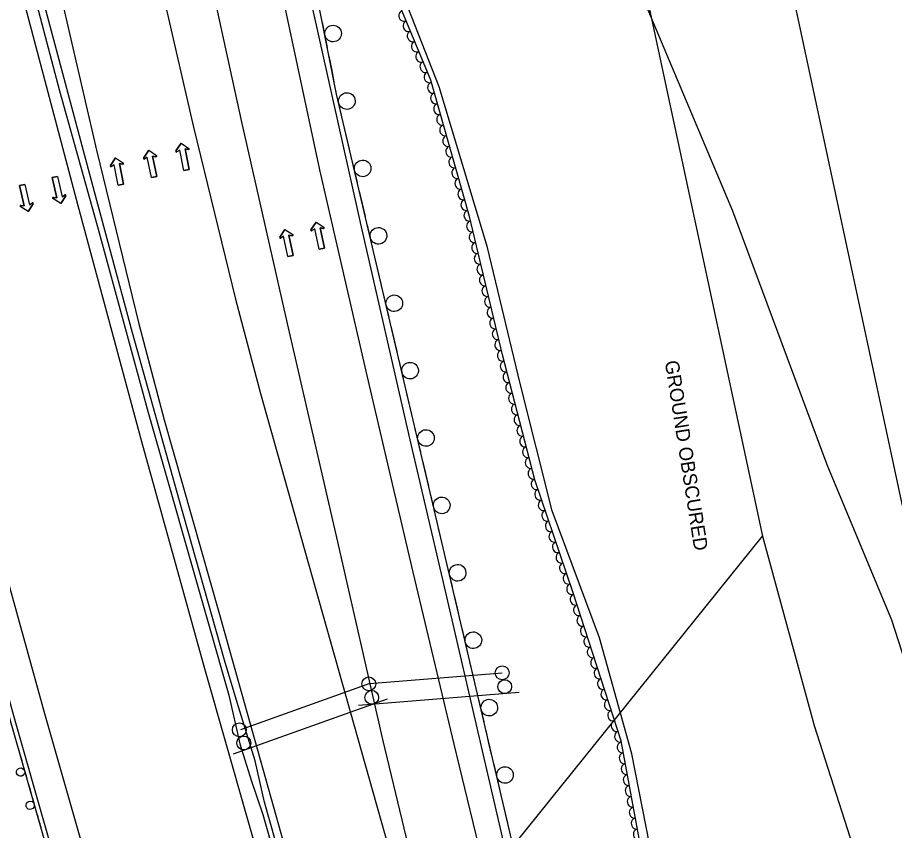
# Model space of a CAD drawing. Extents: x 1746719 to 1766531, y 631721 to 662391.
# Drawn here: x 1753970.5 to 1754287.2, y 650890.3 to 651183.8 of the extents above; entities that cross this region are included whole.
import ezdxf

# ---------------------------------------------------------------- set-up
doc = ezdxf.new("R2010")
doc.units = 0
for name, color, linetype in [('SURVEY - AERIAL SURVEY - Photo Control - Points - Elevations', 7, 'Continuous'), ('SURVEY - AERIAL SURVEY - Photo Control - Points - Locators', 7, 'Continuous'), ('SURVEY - AERIAL SURVEY - Photo Control - Points - Numbers', 7, 'Continuous'), ('SURVEY - AERIAL SURVEY - Photo Control with Text', 7, 'Continuous'), ('SURVEY - CONTROL - Grid', 7, 'Continuous'), ('SURVEY - CONTROL - Points - Locators', 7, 'Continuous')]:
    doc.layers.add(name, color=color, linetype=linetype)

msp = doc.modelspace()

# ---------------------------------------------------------------- linework, layer by layer
at = {"layer": 'SURVEY - AERIAL SURVEY - Photo Control - Points - Elevations'}
for points in [[(1754063.35, 651204.56), (1754079.53, 651128.87), (1754096.68, 651054.56), (1754113.23, 650983.52), (1754128.08, 650921.41), (1754151.45, 650825.16), (1754182.39, 650697.84)], [(1754072.82, 651206.04), (1754094.18, 651109.83), (1754112.14, 651031.33), (1754123.49, 650982.98), (1754145.46, 650887.82), (1754164.53, 650808.3), (1754187.99, 650714.26), (1754218.11, 650592.11), (1754265.98, 650448.02)], [(1754020.74, 651201.91), (1754034.03, 651144.22), (1754049.15, 651082.15), (1754058.18, 651048.02), (1754078.02, 650978.02), (1754103.01, 650889.26), (1754131.48, 650789.68), (1754151.45, 650719.85)], [(1754039.38, 651201.31), (1754051.19, 651146.66), (1754067.85, 651073.3), (1754085.71, 650996.02), (1754102.41, 650922.67), (1754117.55, 650859.55), (1754134.13, 650790.75), (1754151.45, 650719.85)], [(1753972.17, 651192.06), (1753992.25, 651116.01), (1754015.21, 651030.74), (1754038.02, 650948.81), (1754060.55, 650869.78), (1754089.76, 650767.41), (1754112.32, 650689.17), (1754146.8, 650566.94), (1754158.11, 650527.42), (1754160.85, 650517.83)], [(1753985.66, 651193.84), (1753999, 651135.92), (1754014.26, 651073.28), (1754023.46, 651038.51), (1754043.38, 650968.24), (1754068.37, 650879.43), (1754096.87, 650779.78), (1754126.64, 650675.65), (1754149.99, 650593.47), (1754178.2, 650495.46), (1754179.47, 650490.6)], [(1753914.16, 651176.74), (1753934.28, 651100.55), (1753957.34, 651014.89), (1753980.27, 650932.54), (1754002.85, 650853.32), (1754032.08, 650750.87), (1754054.62, 650672.71), (1754094.66, 650530.79)], [(1753903.52, 651173.93), (1753923.65, 651097.71), (1753946.73, 651011.99), (1753969.68, 650929.56), (1753992.27, 650850.31), (1754021.51, 650747.83), (1754044.04, 650669.7), (1754081.42, 650537.19)]]:
    msp.add_lwpolyline(points, dxfattribs=at)
at = {"layer": 'SURVEY - AERIAL SURVEY - Photo Control - Points - Locators'}
for p, q in [((1754027.68, 651135.66), (1754029.56, 651138.47)), ((1754029.56, 651138.47), (1754027.68, 651135.66)), ((1754029.56, 651138.47), (1754032.37, 651136.59)), ((1754029.56, 651138.47), (1754032.37, 651136.59)), ((1754015.99, 651133.1), (1754017.86, 651135.91)), ((1754017.86, 651135.91), (1754015.99, 651133.1)), ((1754017.86, 651135.91), (1754020.67, 651134.04)), ((1754017.86, 651135.91), (1754020.67, 651134.04)), ((1754029.05, 651136), (1754028.03, 651135.32)), ((1754029.05, 651136), (1754028.03, 651135.32)), ((1754030.52, 651128.62), (1754029.05, 651136)), ((1754030.52, 651128.62), (1754029.05, 651136)), ((1754032.18, 651136.14), (1754030.98, 651136.39)), ((1754030.98, 651136.39), (1754032.45, 651129.01)), ((1754032.45, 651129.01), (1754030.98, 651136.39)), ((1754030.98, 651136.39), (1754032.18, 651136.14)), ((1754004.03, 651130.37), (1754005.91, 651133.18)), ((1754005.91, 651133.18), (1754004.03, 651130.37)), ((1754005.91, 651133.18), (1754008.72, 651131.3)), ((1754005.91, 651133.18), (1754008.72, 651131.3)), ((1754017.35, 651133.45), (1754016.33, 651132.76)), ((1754017.35, 651133.45), (1754016.33, 651132.76)), ((1754018.82, 651126.07), (1754017.35, 651133.45)), ((1754018.82, 651126.07), (1754017.35, 651133.45)), ((1754020.49, 651133.59), (1754019.28, 651133.83)), ((1754019.28, 651133.83), (1754020.75, 651126.45)), ((1754020.75, 651126.45), (1754019.28, 651133.83)), ((1754019.28, 651133.83), (1754020.49, 651133.59)), ((1754005.4, 651130.71), (1754004.38, 651130.03)), ((1754005.4, 651130.71), (1754004.38, 651130.03)), ((1754006.87, 651123.34), (1754005.4, 651130.71)), ((1754006.87, 651123.34), (1754005.4, 651130.71)), ((1754008.53, 651130.86), (1754007.33, 651131.1)), ((1754007.33, 651131.1), (1754008.8, 651123.72)), ((1754008.8, 651123.72), (1754007.33, 651131.1)), ((1754007.33, 651131.1), (1754008.53, 651130.86)), ((1754032.45, 651129.01), (1754030.52, 651128.62)), ((1754030.52, 651128.62), (1754032.45, 651129.01)), ((1753983.01, 651126.03), (1753984.93, 651126.46)), ((1753984.93, 651126.46), (1753983.01, 651126.03)), ((1753984.67, 651118.69), (1753983.01, 651126.03)), ((1753983.01, 651126.03), (1753984.67, 651118.69)), ((1753984.93, 651126.46), (1753986.59, 651119.13)), ((1753984.93, 651126.46), (1753986.59, 651119.13)), ((1754020.75, 651126.45), (1754018.82, 651126.07)), ((1754018.82, 651126.07), (1754020.75, 651126.45)), ((1753971.22, 651123.14), (1753973.14, 651123.57)), ((1753973.14, 651123.57), (1753971.22, 651123.14)), ((1753972.88, 651115.8), (1753971.22, 651123.14)), ((1753971.22, 651123.14), (1753972.88, 651115.8)), ((1753973.14, 651123.57), (1753974.79, 651116.24)), ((1753973.14, 651123.57), (1753974.79, 651116.24)), ((1754008.8, 651123.72), (1754006.87, 651123.34)), ((1754006.87, 651123.34), (1754008.8, 651123.72)), ((1753987.94, 651119.5), (1753986.14, 651116.65)), ((1753986.14, 651116.65), (1753987.94, 651119.5)), ((1753986.59, 651119.13), (1753987.59, 651119.84)), ((1753986.59, 651119.13), (1753987.59, 651119.84)), ((1753971.66, 651116.01), (1753972.88, 651115.8)), ((1753972.88, 651115.8), (1753971.66, 651116.01)), ((1753976.15, 651116.61), (1753974.35, 651113.76)), ((1753974.35, 651113.76), (1753976.15, 651116.61)), ((1753974.79, 651116.24), (1753975.8, 651116.95)), ((1753974.79, 651116.24), (1753975.8, 651116.95)), ((1753986.14, 651116.65), (1753983.28, 651118.45)), ((1753986.14, 651116.65), (1753983.28, 651118.45)), ((1753983.46, 651118.9), (1753984.67, 651118.69)), ((1753984.67, 651118.69), (1753983.46, 651118.9)), ((1753974.35, 651113.76), (1753971.49, 651115.56)), ((1753974.35, 651113.76), (1753971.49, 651115.56)), ((1754076.46, 651107.14), (1754078.29, 651109.97)), ((1754078.29, 651109.97), (1754076.46, 651107.14)), ((1754078.29, 651109.97), (1754081.13, 651108.13)), ((1754078.29, 651109.97), (1754081.13, 651108.13)), ((1754065.2, 651104.51), (1754067.04, 651107.34)), ((1754067.04, 651107.34), (1754065.2, 651104.51)), ((1754067.04, 651107.34), (1754069.87, 651105.5)), ((1754067.04, 651107.34), (1754069.87, 651105.5)), ((1754077.82, 651107.49), (1754076.8, 651106.8)), ((1754077.82, 651107.49), (1754076.8, 651106.8)), ((1754079.39, 651100.14), (1754077.82, 651107.49)), ((1754079.39, 651100.14), (1754077.82, 651107.49)), ((1754080.95, 651107.68), (1754079.74, 651107.91)), ((1754079.74, 651107.91), (1754081.31, 651100.55)), ((1754081.31, 651100.55), (1754079.74, 651107.91)), ((1754079.74, 651107.91), (1754080.95, 651107.68)), ((1754066.56, 651104.86), (1754065.55, 651104.17)), ((1754066.56, 651104.86), (1754065.55, 651104.17)), ((1754068.13, 651097.51), (1754066.56, 651104.86)), ((1754068.13, 651097.51), (1754066.56, 651104.86)), ((1754069.69, 651105.05), (1754068.49, 651105.28)), ((1754068.49, 651105.28), (1754070.05, 651097.92)), ((1754070.05, 651097.92), (1754068.49, 651105.28)), ((1754068.49, 651105.28), (1754069.69, 651105.05)), ((1754081.31, 651100.55), (1754079.39, 651100.14)), ((1754079.39, 651100.14), (1754081.31, 651100.55)), ((1754070.05, 651097.92), (1754068.13, 651097.51)), ((1754068.13, 651097.51), (1754070.05, 651097.92))]:
    msp.add_line(p, q, dxfattribs=at)
for points in [[(1754189.03, 651208.12), (1754228.69, 651114.03), (1754262.75, 651022.48), (1754286.04, 650966.3), (1754304.12, 650910.31), (1754324.95, 650850.75), (1754345.91, 650775.28), (1754364.89, 650696.63), (1754384.99, 650630.7), (1754403.46, 650583.55), (1754431.21, 650499.72), (1754438.06, 650449.83), (1754446.98, 650357.55)], [(1754289.04, 650635.59), (1754285.74, 650671.74), (1754281.36, 650715.71), (1754272.07, 650753.89), (1754248.97, 650769.35), (1754231.19, 650774.34), (1754216.19, 650821.21), (1754201.2, 650872.56), (1754192.32, 650917.96), (1754180.65, 650959.8), (1754163.54, 651005.75), (1754152.03, 651051.69), (1754140.15, 651100.82), (1754122.75, 651158.86), (1754106.53, 651200.34)]]:
    msp.add_lwpolyline(points, dxfattribs=at)
for centre, start, end in [((1754027.89, 651135.52), 146.2595, 303.7527), ((1754027.89, 651135.52), 146.2595, 303.7527), ((1754032.23, 651136.39), 258.8112, 56.2595), ((1754032.23, 651136.39), 258.8112, 56.2595), ((1754016.19, 651132.97), 146.2595, 303.7527), ((1754016.19, 651132.97), 146.2595, 303.7527), ((1754020.54, 651133.83), 258.8112, 56.2595), ((1754020.54, 651133.83), 258.8112, 56.2595), ((1754004.24, 651130.24), 146.2595, 303.7527), ((1754004.24, 651130.24), 146.2595, 303.7527), ((1754008.58, 651131.1), 258.8112, 56.2595), ((1754008.58, 651131.1), 258.8112, 56.2595), ((1753987.73, 651119.63), 327.7185, 125.2117), ((1753987.73, 651119.63), 327.7185, 125.2117), ((1753971.62, 651115.77), 80.2702, 237.7185), ((1753971.62, 651115.77), 80.2702, 237.7185), ((1753975.94, 651116.74), 327.7185, 125.2117), ((1753975.94, 651116.74), 327.7185, 125.2117), ((1753983.41, 651118.66), 80.2702, 237.7185), ((1753983.41, 651118.66), 80.2702, 237.7185), ((1754076.66, 651107), 147.0491, 304.5422), ((1754076.66, 651107), 147.0491, 304.5422), ((1754080.99, 651107.93), 259.6008, 57.0491), ((1754080.99, 651107.93), 259.6008, 57.0491), ((1754065.41, 651104.37), 147.0491, 304.5422), ((1754065.41, 651104.37), 147.0491, 304.5422), ((1754069.74, 651105.29), 259.6008, 57.0491), ((1754069.74, 651105.29), 259.6008, 57.0491)]:
    msp.add_arc(centre, 0.246, start, end, dxfattribs=at)
at = {"layer": 'SURVEY - AERIAL SURVEY - Photo Control - Points - Numbers'}
for points in [[(1754277.22, 650442.59), (1754261.86, 650465.35), (1754221.06, 650591.52), (1754167.3, 650808.68), (1754121.44, 651004.08), (1754085.73, 651156.22), (1754055.64, 651308.03), (1754019.01, 651484.3)], [(1753976.4, 651192.62), (1753985.63, 651157.37), (1753999.56, 651107.38), (1754017.65, 651041.27), (1754039.67, 650963.99), (1754046.76, 650939.07), (1754050.77, 650921.6), (1754055, 650908.04), (1754059.02, 650896.07), (1754079.37, 650824.52), (1754099.29, 650754.42), (1754120.26, 650679.29), (1754139.53, 650612.32), (1754166.51, 650517.9)], [(1754175.8, 650492.56), (1754160.24, 650546.46), (1754142.04, 650609.69), (1754125.24, 650668.34), (1754110.86, 650720.6), (1754096.24, 650772.39), (1754077.82, 650836.36), (1754059.64, 650900.45), (1754056.28, 650915.36), (1754049.84, 650936.52), (1754045.21, 650951.78), (1754029.02, 651009.31), (1754011.97, 651069.98), (1753996.6, 651127.12), (1753979.08, 651193.03)], [(1754082.4, 651173.03), (1754080.61, 651182.06)], [(1753901.95, 651173.51), (1753922.08, 651097.29), (1753945.17, 651011.56), (1753968.12, 650929.12), (1753990.71, 650849.86), (1754019.95, 650747.38), (1754042.48, 650669.25), (1754079.47, 650538.13)], [(1754083.94, 651165.28), (1754083.02, 651169.89)], [(1754084.85, 651160.67), (1754083.94, 651165.28)], [(1754087.53, 651148.57), (1754085.73, 651156.22), (1754085.47, 651157.54)], [(1754089.33, 651140.88), (1754088.26, 651145.45)], [(1754090.41, 651136.3), (1754089.33, 651140.88)], [(1754093.24, 651124.23), (1754091.14, 651133.19)], [(1754095.05, 651116.54), (1754093.97, 651121.11)], [(1754096.12, 651111.96), (1754095.05, 651116.54)], [(1754098.95, 651099.89), (1754096.85, 651108.85)], [(1754100.76, 651092.2), (1754099.68, 651096.78)], [(1754101.83, 651087.62), (1754100.76, 651092.2)], [(1754104.66, 651075.55), (1754102.56, 651084.51)], [(1754106.47, 651067.86), (1754105.4, 651072.44)], [(1754107.54, 651063.29), (1754106.47, 651067.86)], [(1754110.38, 651051.21), (1754108.27, 651060.17)], [(1754112.18, 651043.52), (1754111.11, 651048.1)], [(1754113.26, 651038.95), (1754112.18, 651043.52)], [(1754116.09, 651026.87), (1754113.99, 651035.83)], [(1754117.89, 651019.18), (1754116.82, 651023.76)], [(1754118.97, 651014.61), (1754117.89, 651019.18)], [(1754121.8, 651002.54), (1754121.44, 651004.08), (1754119.7, 651011.49)], [(1754123.6, 650994.84), (1754122.53, 650999.42)], [(1754124.68, 650990.27), (1754123.6, 650994.84)], [(1754127.51, 650978.2), (1754125.41, 650987.15)], [(1754129.32, 650970.51), (1754128.24, 650975.08)], [(1754130.39, 650965.93), (1754129.32, 650970.51)], [(1754133.22, 650953.86), (1754131.12, 650962.81)], [(1754135.03, 650946.17), (1754133.96, 650950.74)], [(1754136.1, 650941.59), (1754135.03, 650946.17)], [(1754138.94, 650929.52), (1754136.83, 650938.48)], [(1754140.74, 650921.83), (1754139.67, 650926.4)], [(1753970.72, 650920.02), (1753971.36, 650917.76)], [(1754141.82, 650917.25), (1754140.74, 650921.83)], [(1753971.36, 650917.76), (1753972, 650915.5)], [(1753972.44, 650913.96), (1753973.7, 650909.54)], [(1754144.65, 650905.18), (1754142.55, 650914.14)], [(1753974.14, 650908), (1753974.79, 650905.74)], [(1753974.79, 650905.74), (1753975.43, 650903.48)], [(1753975.87, 650901.94), (1753977.13, 650897.52)], [(1754146.45, 650897.49), (1754145.38, 650902.07)], [(1754147.53, 650892.91), (1754146.45, 650897.49)], [(1753977.57, 650895.98), (1753978.21, 650893.72)], [(1753978.21, 650893.72), (1753978.86, 650891.46)]]:
    msp.add_lwpolyline(points, dxfattribs=at)
for centre, radius, start, end in [((1754084.46, 651178.08), 3, 304.4806, 304.4666), ((1754089.41, 651153.69), 3, 306.475, 306.461), ((1754095.12, 651129.35), 3, 306.475, 306.461), ((1754100.83, 651105.01), 3, 306.475, 306.461), ((1754106.54, 651080.67), 3, 306.475, 306.461), ((1754112.26, 651056.33), 3, 306.475, 306.461), ((1754117.97, 651031.99), 3, 306.475, 306.461), ((1754123.68, 651007.66), 3, 306.475, 306.461), ((1754129.39, 650983.32), 3, 306.4774, 306.4634), ((1754135.1, 650958.98), 3, 306.4774, 306.4634), ((1754140.82, 650934.64), 3, 306.4774, 306.4634), ((1754146.53, 650910.3), 3, 306.4774, 306.4634), ((1753971.62, 650911.36), 1.5, 129.1679, 129.1581), ((1753975.05, 650899.34), 1.5, 129.1679, 129.1581)]:
    msp.add_arc(centre, radius, start, end, dxfattribs=at)
at = {"layer": 'SURVEY - AERIAL SURVEY - Photo Control with Text'}
msp.add_lwpolyline([(1754437.51, 650352.91), (1754373.46, 650364.73), (1754342.18, 650371.08), (1754330.7, 650387.52), (1754322.19, 650421.14), (1754324.94, 650470.68), (1754320.13, 650524.69), (1754316.48, 650564.69), (1754305.81, 650600.41), (1754286.82, 650634.23), (1754280.52, 650686.12), (1754274.54, 650724.16), (1754269.28, 650750.14), (1754249.03, 650765.51), (1754227.91, 650772.31), (1754210.67, 650824.74), (1754196.82, 650877.62), (1754188.5, 650922.64), (1754171.01, 650976.43), (1754157.32, 651016.92), (1754145.6, 651062.07), (1754133.69, 651111.97), (1754119.69, 651161.21), (1754098.48, 651212.49)], dxfattribs=at)
for centre, major_axis in [((1754110.06, 651184.48), (-0.76, 1.85)), ((1754111.59, 651180.78), (-0.76, 1.85)), ((1754113.12, 651177.08), (-0.76, 1.85)), ((1754114.65, 651173.39), (-0.76, 1.85)), ((1754116.18, 651169.69), (-0.76, 1.85)), ((1754117.71, 651165.99), (-0.76, 1.85)), ((1754119.23, 651162.3), (-0.76, 1.85)), ((1754120.46, 651158.5), (-0.55, 1.92)), ((1754121.55, 651154.65), (-0.55, 1.92)), ((1754122.65, 651150.8), (-0.55, 1.92)), ((1754123.74, 651146.95), (-0.55, 1.92)), ((1754124.83, 651143.11), (-0.55, 1.92)), ((1754125.93, 651139.26), (-0.55, 1.92)), ((1754127.02, 651135.41), (-0.55, 1.92)), ((1754128.12, 651131.56), (-0.55, 1.92)), ((1754129.21, 651127.72), (-0.55, 1.92)), ((1754130.31, 651123.87), (-0.55, 1.92)), ((1754131.4, 651120.02), (-0.55, 1.92)), ((1754132.49, 651116.17), (-0.55, 1.92)), ((1754133.59, 651112.33), (-0.55, 1.92)), ((1754134.53, 651108.44), (-0.46, 1.95)), ((1754135.46, 651104.55), (-0.46, 1.95)), ((1754136.39, 651100.66), (-0.46, 1.95)), ((1754137.32, 651096.77), (-0.46, 1.95)), ((1754138.25, 651092.88), (-0.46, 1.95)), ((1754139.17, 651088.99), (-0.46, 1.95)), ((1754140.1, 651085.1), (-0.46, 1.95)), ((1754141.03, 651081.2), (-0.46, 1.95)), ((1754141.96, 651077.31), (-0.46, 1.95)), ((1754142.89, 651073.42), (-0.46, 1.95)), ((1754143.82, 651069.53), (-0.46, 1.95)), ((1754144.74, 651065.64), (-0.46, 1.95)), ((1754145.68, 651061.75), (-0.5, 1.94)), ((1754146.68, 651057.88), (-0.5, 1.94)), ((1754147.69, 651054.01), (-0.5, 1.94)), ((1754148.7, 651050.14), (-0.5, 1.94)), ((1754149.7, 651046.27), (-0.5, 1.94)), ((1754150.71, 651042.39), (-0.5, 1.94)), ((1754151.71, 651038.52), (-0.5, 1.94)), ((1754152.72, 651034.65), (-0.5, 1.94)), ((1754153.72, 651030.78), (-0.5, 1.94)), ((1754154.73, 651026.91), (-0.5, 1.94)), ((1754155.73, 651023.04), (-0.5, 1.94)), ((1754156.74, 651019.16), (-0.5, 1.94)), ((1754157.86, 651015.33), (-0.64, 1.89)), ((1754159.14, 651011.54), (-0.64, 1.89)), ((1754160.42, 651007.75), (-0.64, 1.89)), ((1754161.7, 651003.96), (-0.64, 1.89)), ((1754162.99, 651000.17), (-0.64, 1.89)), ((1754164.27, 650996.38), (-0.64, 1.89)), ((1754165.55, 650992.59), (-0.64, 1.89)), ((1754166.83, 650988.8), (-0.64, 1.89)), ((1754168.11, 650985.01), (-0.64, 1.89)), ((1754169.39, 650981.22), (-0.64, 1.89)), ((1754170.67, 650977.44), (-0.64, 1.89)), ((1754171.92, 650973.64), (-0.62, 1.9)), ((1754173.16, 650969.83), (-0.62, 1.9)), ((1754174.39, 650966.03), (-0.62, 1.9)), ((1754175.63, 650962.22), (-0.62, 1.9)), ((1754176.87, 650958.42), (-0.62, 1.9)), ((1754178.1, 650954.61), (-0.62, 1.9)), ((1754179.34, 650950.81), (-0.62, 1.9)), ((1754180.58, 650947.01), (-0.62, 1.9)), ((1754181.81, 650943.2), (-0.62, 1.9)), ((1754183.05, 650939.4), (-0.62, 1.9)), ((1754184.29, 650935.59), (-0.62, 1.9)), ((1754185.52, 650931.79), (-0.62, 1.9)), ((1754186.76, 650927.99), (-0.62, 1.9)), ((1754187.99, 650924.18), (-0.62, 1.9)), ((1754188.93, 650920.3), (-0.36, 1.97)), ((1754189.66, 650916.37), (-0.36, 1.97)), ((1754190.38, 650912.43), (-0.36, 1.97)), ((1754191.11, 650908.5), (-0.36, 1.97)), ((1754191.84, 650904.57), (-0.36, 1.97)), ((1754192.56, 650900.63), (-0.36, 1.97)), ((1754193.29, 650896.7), (-0.36, 1.97)), ((1754194.02, 650892.77), (-0.36, 1.97)), ((1754194.75, 650888.83), (-0.36, 1.97))]:
    msp.add_ellipse(centre, major_axis=major_axis, ratio=0.940188, start_param=0, end_param=3.141593, dxfattribs=at)
at = {"layer": 'SURVEY - CONTROL - Grid'}
for p, q in [((1754145.49, 650947.17), (1754145.49, 650947.17)), ((1754145.49, 650947.17), (1754145.49, 650947.17)), ((1754097.72, 650943.38), (1754051.02, 650926.57)), ((1754097.72, 650943.38), (1754051.02, 650926.57)), ((1754097.3, 650943.18), (1754097.3, 650943.18)), ((1754097.3, 650943.18), (1754097.3, 650943.18)), ((1754146.41, 650942.19), (1754146.41, 650942.19)), ((1754146.41, 650942.19), (1754146.41, 650942.19)), ((1754151.58, 650940.09), (1754093.62, 650935.42)), ((1754103.93, 650937.64), (1754048.35, 650917.8)), ((1754098.39, 650938.32), (1754098.39, 650938.32)), ((1754098.39, 650938.32), (1754098.39, 650938.32)), ((1754050.58, 650926.6), (1754050.58, 650926.6)), ((1754050.58, 650926.6), (1754050.58, 650926.6)), ((1754052.21, 650921.83), (1754052.21, 650921.83)), ((1754052.21, 650921.83), (1754052.21, 650921.83))]:
    msp.add_line(p, q, dxfattribs=at)
msp.add_lwpolyline([(1754097.72, 650943.38), (1754145.49, 650947.17)], dxfattribs=at)
msp.add_lwpolyline([(1754097.72, 650943.38), (1754145.49, 650947.17)], dxfattribs=at)
for centre in [(1754145.5, 650947.19), (1754145.5, 650947.19), (1754097.32, 650943.19), (1754097.32, 650943.19), (1754146.42, 650942.2), (1754146.42, 650942.2), (1754098.4, 650938.33), (1754098.4, 650938.33), (1754050.6, 650926.62), (1754050.6, 650926.62), (1754052.22, 650921.85), (1754052.22, 650921.85)]:
    msp.add_circle(centre, 2.5, dxfattribs=at)
at = {"layer": 'SURVEY - CONTROL - Points - Locators'}
for points in [[(1754355.39, 651800.12), (1754279.49, 651732.05), (1754250.7, 651685.75), (1754218.54, 651615.28), (1754190.08, 651536.67), (1754169.64, 651454.54), (1754162.69, 651391.74), (1754167.28, 651333.43), (1754239.48, 650996.5), (1754258.15, 650928.17), (1754277.98, 650866.22), (1754308.69, 650819.4), (1754334.91, 650784.12), (1754384.39, 650741.68), (1754438.42, 650718.28), (1754518.34, 650691.93), (1754607.58, 650664.15), (1754710.2, 650648.48)], [(1754389.89, 651761.65), (1754319.48, 651698.5), (1754296.33, 651661.28), (1754262.05, 651598.43), (1754247.41, 651506.85), (1754220.62, 651445.41), (1754214.59, 651390.92), (1754218.53, 651340.91), (1754289.71, 651008.73), (1754307.7, 650942.87), (1754325.06, 650888.68), (1754351.07, 650849.01), (1754367.14, 650811.09), (1754406.29, 650777.49), (1754456.82, 650766.63), (1754530.29, 650748.7), (1754619.23, 650714.65), (1754717.99, 650699.57)], [(1753788.95, 650384.07), (1753825.28, 650445.89), (1753839.88, 650455.8), (1753871.89, 650458.05), (1753890.56, 650472.81), (1753957.31, 650610.67), (1753992.12, 650669.75), (1754086.14, 650805.93), (1754239.48, 650996.5)]]:
    msp.add_lwpolyline(points, dxfattribs=at)

# ---------------------------------------------------------------- texts
at = {"layer": 'SURVEY - AERIAL SURVEY - Photo Control - Points - Locators'}
msp.add_text('GROUND OBSCURED', height=5, rotation=278.887, dxfattribs=at).set_placement((1754204.21, 651059.63))

doc.saveas('drawing.dxf')
